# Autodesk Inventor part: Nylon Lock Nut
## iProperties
Title: Nylon Lock Nut
Author: QBZ
Created: 2001-04
Part Number: 351_3514
Material: Steel, Mild
Description: 5/16 Std NC Nylock Nut
Document SubType Name: Modeling
Designer: QBZ
Category: Fasteners
Control State: 0
Master: False
Checked Out: False
Last Check In Date: 2002-01-29
PropertySet Name: Design Tracking Control
Last Check In By: tomm
Shininess: 70.0
PropertySet Name: _Private Model Information
Density: 7.859999999999999
Volumn: 40.07686313737254
Area: 115.62685411210367
PropertySet Name: Model Information
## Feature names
1. Extrusion1
2. Revolution1
3. Extrusion2
4. Revolution2
